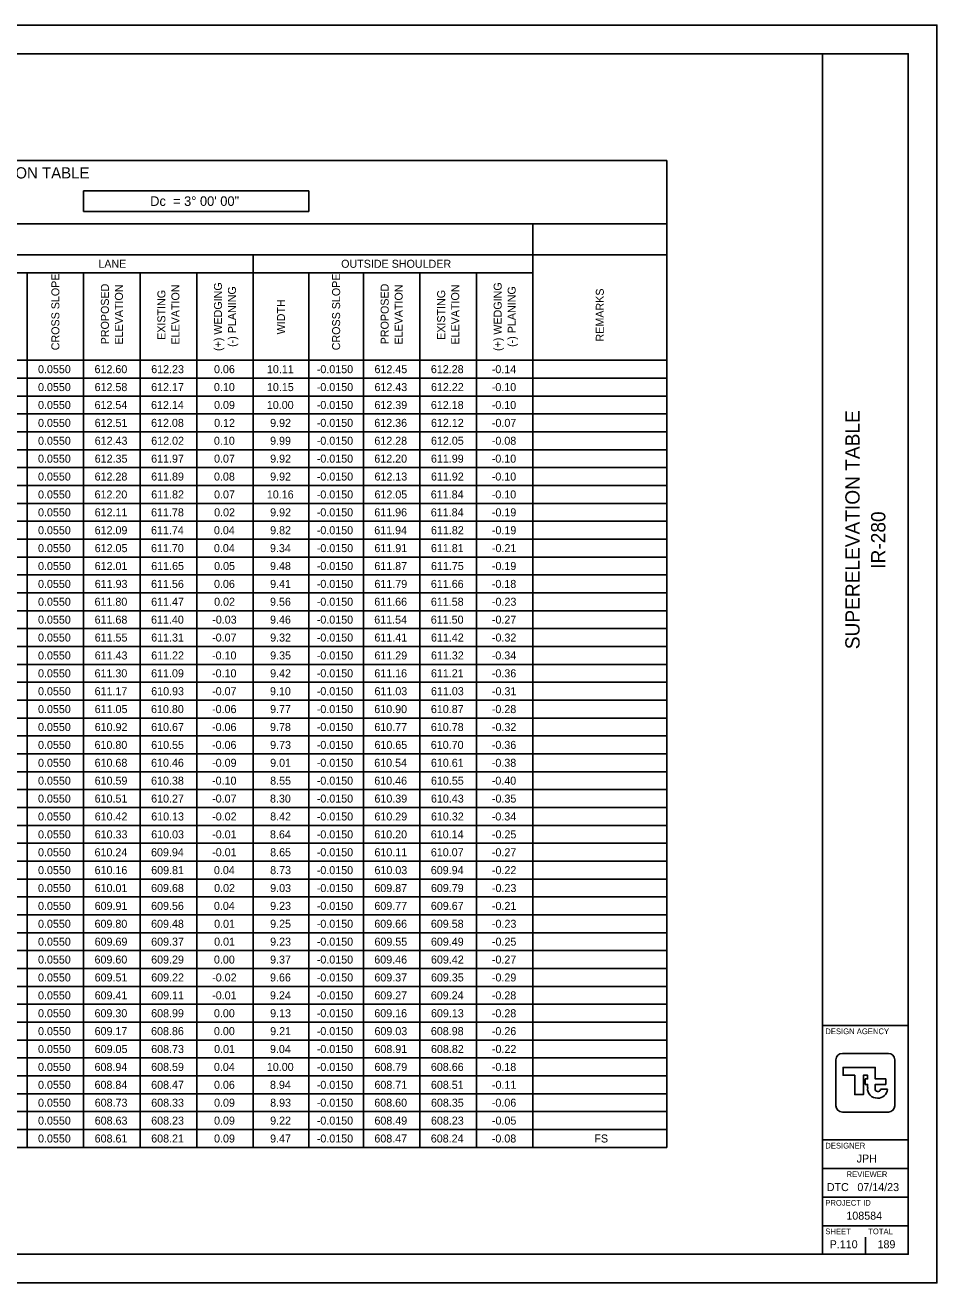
# Model space of a CAD drawing. Extents: x 0 to 34, y 0 to 22.
# Drawn here: x 18.06 to 34, y 0 to 22 of the extents above; entities that cross this region are included whole.
import ezdxf

# ---------------------------------------------------------------- set-up
doc = ezdxf.new("R2010")
doc.units = 0
for name, color, linetype in [('Default', 7, 'Continuous'), ('SH_Border', 7, 'Continuous'), ('SH_Cut_Line', 7, 'Continuous'), ('SH_Data', 7, 'Continuous')]:
    doc.layers.add(name, color=color, linetype=linetype)

msp = doc.modelspace()

# ---------------------------------------------------------------- linework, layer by layer
at = {"layer": 'Default'}
for p, q in [((4.225, 19.63), (29.277, 19.63)), ((29.277, 19.63), (29.277, 2.369)), ((19.081, 19.103), (23.018, 19.103)), ((19.081, 19.103), (19.081, 18.741)), ((23.018, 19.103), (23.018, 18.741)), ((19.081, 18.741), (23.018, 18.741)), ((4.225, 18.526), (29.277, 18.526)), ((26.938, 18.526), (26.938, 2.369)), ((4.225, 17.983), (29.277, 17.983)), ((22.046, 17.983), (22.046, 2.369)), ((6.3, 17.67), (26.938, 17.67)), ((18.093, 17.67), (18.093, 2.369)), ((19.081, 17.67), (19.081, 2.369)), ((20.07, 17.67), (20.07, 2.369)), ((21.058, 17.67), (21.058, 2.369)), ((23.018, 17.67), (23.018, 2.369)), ((23.973, 17.67), (23.973, 2.369)), ((24.961, 17.67), (24.961, 2.369)), ((25.95, 17.67), (25.95, 2.369)), ((4.225, 16.138), (29.277, 16.138)), ((4.225, 15.825), (29.277, 15.825)), ((4.225, 15.512), (29.277, 15.512)), ((4.225, 15.199), (29.277, 15.199)), ((4.225, 14.886), (29.277, 14.886)), ((4.225, 14.574), (29.277, 14.574)), ((4.225, 14.261), (29.277, 14.261)), ((4.225, 13.948), (29.277, 13.948)), ((4.225, 13.635), (29.277, 13.635)), ((4.225, 13.322), (29.277, 13.322)), ((4.225, 13.009), (29.277, 13.009)), ((4.225, 12.696), (29.277, 12.696)), ((4.225, 12.383), (29.277, 12.383)), ((4.225, 12.07), (29.277, 12.07)), ((4.225, 11.757), (29.277, 11.757)), ((4.225, 11.444), (29.277, 11.444)), ((4.225, 11.131), (29.277, 11.131)), ((4.225, 10.818), (29.277, 10.818)), ((4.225, 10.505), (29.277, 10.505)), ((4.225, 10.192), (29.277, 10.192)), ((4.225, 9.879), (29.277, 9.879)), ((4.225, 9.566), (29.277, 9.566)), ((4.225, 9.254), (29.277, 9.254)), ((4.225, 8.941), (29.277, 8.941)), ((4.225, 8.628), (29.277, 8.628)), ((4.225, 8.315), (29.277, 8.315)), ((4.225, 8.002), (29.277, 8.002)), ((4.225, 7.689), (29.277, 7.689)), ((4.225, 7.376), (29.277, 7.376)), ((4.225, 7.063), (29.277, 7.063)), ((4.225, 6.75), (29.277, 6.75)), ((4.225, 6.437), (29.277, 6.437)), ((4.225, 6.124), (29.277, 6.124)), ((4.225, 5.811), (29.277, 5.811)), ((4.225, 5.498), (29.277, 5.498)), ((4.225, 5.185), (29.277, 5.185)), ((4.225, 4.872), (29.277, 4.872)), ((4.225, 4.559), (29.277, 4.559)), ((4.225, 4.246), (29.277, 4.246)), ((4.225, 3.934), (29.277, 3.934)), ((4.225, 3.621), (29.277, 3.621)), ((4.225, 3.308), (29.277, 3.308)), ((4.225, 2.995), (29.277, 2.995)), ((4.225, 2.682), (29.277, 2.682)), ((4.225, 2.369), (29.277, 2.369))]:
    msp.add_line(p, q, dxfattribs=at)
at = {"layer": 'SH_Border'}
for p, q in [((32, 0.5), (32, 21.5)), ((32, 4.5), (33.5, 4.5)), ((32, 2.5), (33.5, 2.5)), ((32, 2), (33.5, 2)), ((32, 1.5), (33.5, 1.5)), ((32, 1), (33.5, 1))]:
    msp.add_line(p, q, dxfattribs=at)
msp.add_lwpolyline([(1.5, 21.5), (33.5, 21.5), (33.5, 0.5), (1.5, 0.5)], close=True, dxfattribs=at)
at = {"layer": 'SH_Cut_Line'}
msp.add_lwpolyline([(0, 0), (34, 0), (34, 22), (0, 22)], close=True, dxfattribs=at)
at = {"layer": 'SH_Data'}
for p, q in [((32.75, 3.5), (32.75, 3.5)), ((32.791, 3.415), (32.791, 3.415)), ((33.136, 3.385), (33.015, 3.385)), ((32.375, 0.675), (32.375, 0.675)), ((32.75, 0.5), (32.75, 0.8))]:
    msp.add_line(p, q, dxfattribs=at)
for points in [[(32.348, 4.014), (33.152, 4.014)], [(32.236, 3.099), (32.236, 3.901)], [(32.922, 3.399), (32.922, 3.47), (33.107, 3.47), (33.107, 3.568), (32.922, 3.568), (32.922, 3.768), (32.361, 3.768), (32.361, 3.632), (32.566, 3.632), (32.566, 3.294), (32.715, 3.294), (32.715, 3.63), (32.79, 3.63), (32.79, 3.568), (32.748, 3.568), (32.748, 3.47), (32.79, 3.47), (32.79, 3.415), (32.791, 3.415)], [(33.264, 3.901), (33.264, 3.099)], [(33.152, 2.986), (32.348, 2.986)]]:
    msp.add_lwpolyline(points, dxfattribs=at)
for centre, radius, start, end in [((32.348, 3.901), 0.113, 90, 180), ((33.152, 3.901), 0.113, 360, 90), ((32.949, 3.392), 0.16, 171.8856, 274.8323), ((32.968, 3.392), 0.0473, 171.8856, 350.9243), ((32.976, 3.392), 0.16, 265.1677, 357.3201), ((32.348, 3.099), 0.113, 180, 270), ((33.152, 3.099), 0.113, 270, 360)]:
    msp.add_arc(centre, radius, start, end, dxfattribs=at)

# ---------------------------------------------------------------- texts
at = {"layer": 'Default'}
for s, height, p in [('WOO/LUC-280-06.20/00.00 - SUPERELEVATION TABLE', 0.196, (12.425, 19.318)), ('Dc  = 3° 00\' 00"', 0.168, (20.245, 18.838)), ('LANE', 0.14, (19.338, 17.756)), ('OUTSIDE SHOULDER', 0.14, (23.584, 17.756)), ('0.0550', 0.14, (18.284, 15.912)), ('612.60', 0.14, (19.272, 15.912)), ('612.23', 0.14, (20.263, 15.912)), ('0.06', 0.14, (21.361, 15.912)), ('10.11', 0.14, (22.287, 15.912)), ('-0.0150', 0.14, (23.158, 15.912)), ('612.45', 0.14, (24.167, 15.912)), ('612.28', 0.14, (25.153, 15.912)), ('-0.14', 0.14, (26.218, 15.912)), ('0.0550', 0.14, (18.284, 15.599)), ('612.58', 0.14, (19.273, 15.599)), ('612.17', 0.14, (20.262, 15.599)), ('0.10', 0.14, (21.36, 15.599)), ('10.15', 0.14, (22.287, 15.599)), ('-0.0150', 0.14, (23.158, 15.599)), ('612.43', 0.14, (24.167, 15.599)), ('612.22', 0.14, (25.155, 15.599)), ('-0.10', 0.14, (26.218, 15.599)), ('0.0550', 0.14, (18.284, 15.286)), ('612.54', 0.14, (19.272, 15.286)), ('612.14', 0.14, (20.26, 15.286)), ('0.09', 0.14, (21.362, 15.286)), ('10.00', 0.14, (22.285, 15.286)), ('-0.0150', 0.14, (23.158, 15.286)), ('612.39', 0.14, (24.166, 15.286)), ('612.18', 0.14, (25.153, 15.286)), ('-0.10', 0.14, (26.218, 15.286)), ('0.0550', 0.14, (18.284, 14.973)), ('612.51', 0.14, (19.274, 14.973)), ('612.08', 0.14, (20.261, 14.973)), ('0.12', 0.14, (21.363, 14.973)), ('9.92', 0.14, (22.343, 14.973)), ('-0.0150', 0.14, (23.158, 14.973)), ('612.36', 0.14, (24.164, 14.973)), ('612.12', 0.14, (25.155, 14.973)), ('-0.07', 0.14, (26.22, 14.973)), ('0.0550', 0.14, (18.284, 14.66)), ('612.43', 0.14, (19.275, 14.66)), ('612.02', 0.14, (20.263, 14.66)), ('0.10', 0.14, (21.36, 14.66)), ('9.99', 0.14, (22.342, 14.66)), ('-0.0150', 0.14, (23.158, 14.66)), ('612.28', 0.14, (24.165, 14.66)), ('612.05', 0.14, (25.155, 14.66)), ('-0.08', 0.14, (26.219, 14.66)), ('0.0550', 0.14, (18.284, 14.347)), ('612.35', 0.14, (19.275, 14.347)), ('611.97', 0.14, (20.262, 14.347)), ('0.07', 0.14, (21.362, 14.347)), ('9.92', 0.14, (22.343, 14.347)), ('-0.0150', 0.14, (23.158, 14.347)), ('612.20', 0.14, (24.164, 14.347)), ('611.99', 0.14, (25.154, 14.347)), ('-0.10', 0.14, (26.218, 14.347)), ('0.0550', 0.14, (18.284, 14.034)), ('612.28', 0.14, (19.273, 14.034)), ('611.89', 0.14, (20.262, 14.034)), ('0.08', 0.14, (21.361, 14.034)), ('9.92', 0.14, (22.343, 14.034)), ('-0.0150', 0.14, (23.158, 14.034)), ('612.13', 0.14, (24.167, 14.034)), ('611.92', 0.14, (25.155, 14.034)), ('-0.10', 0.14, (26.218, 14.034)), ('0.0550', 0.14, (18.284, 13.721)), ('612.20', 0.14, (19.272, 13.721)), ('611.82', 0.14, (20.263, 13.721)), ('0.07', 0.14, (21.362, 13.721)), ('10.16', 0.14, (22.285, 13.721)), ('-0.0150', 0.14, (23.158, 13.721)), ('612.05', 0.14, (24.167, 13.721)), ('611.84', 0.14, (25.152, 13.721)), ('-0.10', 0.14, (26.218, 13.721)), ('0.0550', 0.14, (18.284, 13.408)), ('612.11', 0.14, (19.274, 13.408)), ('611.78', 0.14, (20.261, 13.408)), ('0.02', 0.14, (21.363, 13.408)), ('9.92', 0.14, (22.343, 13.408)), ('-0.0150', 0.14, (23.158, 13.408)), ('611.96', 0.14, (24.164, 13.408)), ('611.84', 0.14, (25.152, 13.408)), ('-0.19', 0.14, (26.22, 13.408)), ('0.0550', 0.14, (18.284, 13.095)), ('612.09', 0.14, (19.274, 13.095)), ('611.74', 0.14, (20.26, 13.095)), ('0.04', 0.14, (21.36, 13.095)), ('9.82', 0.14, (22.343, 13.095)), ('-0.0150', 0.14, (23.158, 13.095)), ('611.94', 0.14, (24.163, 13.095)), ('611.82', 0.14, (25.155, 13.095)), ('-0.19', 0.14, (26.22, 13.095)), ('0.0550', 0.14, (18.284, 12.782)), ('612.05', 0.14, (19.275, 12.782)), ('611.70', 0.14, (20.26, 12.782)), ('0.04', 0.14, (21.36, 12.782)), ('9.34', 0.14, (22.34, 12.782)), ('-0.0150', 0.14, (23.158, 12.782)), ('611.91', 0.14, (24.166, 12.782)), ('611.81', 0.14, (25.154, 12.782)), ('-0.21', 0.14, (26.221, 12.782)), ('0.0550', 0.14, (18.284, 12.469)), ('612.01', 0.14, (19.274, 12.469)), ('611.65', 0.14, (20.263, 12.469)), ('0.05', 0.14, (21.363, 12.469)), ('9.48', 0.14, (22.341, 12.469)), ('-0.0150', 0.14, (23.158, 12.469)), ('611.87', 0.14, (24.165, 12.469)), ('611.75', 0.14, (25.155, 12.469)), ('-0.19', 0.14, (26.22, 12.469)), ('0.0550', 0.14, (18.284, 12.156)), ('611.93', 0.14, (19.275, 12.156)), ('611.56', 0.14, (20.261, 12.156)), ('0.06', 0.14, (21.361, 12.156)), ('9.41', 0.14, (22.343, 12.156)), ('-0.0150', 0.14, (23.158, 12.156)), ('611.79', 0.14, (24.166, 12.156)), ('611.66', 0.14, (25.153, 12.156)), ('-0.18', 0.14, (26.219, 12.156)), ('0.0550', 0.14, (18.284, 11.844)), ('611.80', 0.14, (19.272, 11.844)), ('611.47', 0.14, (20.262, 11.844)), ('0.02', 0.14, (21.363, 11.844)), ('9.56', 0.14, (22.341, 11.844)), ('-0.0150', 0.14, (23.158, 11.844)), ('611.66', 0.14, (24.164, 11.844)), ('611.58', 0.14, (25.153, 11.844)), ('-0.23', 0.14, (26.221, 11.844)), ('0.0550', 0.14, (18.284, 11.531)), ('611.68', 0.14, (19.273, 11.531)), ('611.40', 0.14, (20.26, 11.531)), ('-0.03', 0.14, (21.33, 11.531)), ('9.46', 0.14, (22.341, 11.531)), ('-0.0150', 0.14, (23.158, 11.531)), ('611.54', 0.14, (24.163, 11.531)), ('611.50', 0.14, (25.152, 11.531)), ('-0.27', 0.14, (26.22, 11.531)), ('0.0550', 0.14, (18.284, 11.218)), ('611.55', 0.14, (19.275, 11.218)), ('611.31', 0.14, (20.263, 11.218)), ('-0.07', 0.14, (21.328, 11.218)), ('9.32', 0.14, (22.343, 11.218)), ('-0.0150', 0.14, (23.158, 11.218)), ('611.41', 0.14, (24.166, 11.218)), ('611.42', 0.14, (25.155, 11.218)), ('-0.32', 0.14, (26.221, 11.218)), ('0.0550', 0.14, (18.284, 10.905)), ('611.43', 0.14, (19.275, 10.905)), ('611.22', 0.14, (20.263, 10.905)), ('-0.10', 0.14, (21.327, 10.905)), ('9.35', 0.14, (22.343, 10.905)), ('-0.0150', 0.14, (23.158, 10.905)), ('611.29', 0.14, (24.166, 10.905)), ('611.32', 0.14, (25.155, 10.905)), ('-0.34', 0.14, (26.218, 10.905)), ('0.0550', 0.14, (18.284, 10.592)), ('611.30', 0.14, (19.272, 10.592)), ('611.09', 0.14, (20.262, 10.592)), ('-0.10', 0.14, (21.327, 10.592)), ('9.42', 0.14, (22.343, 10.592)), ('-0.0150', 0.14, (23.158, 10.592)), ('611.16', 0.14, (24.164, 10.592)), ('611.21', 0.14, (25.154, 10.592)), ('-0.36', 0.14, (26.219, 10.592)), ('0.0550', 0.14, (18.284, 10.279)), ('611.17', 0.14, (19.273, 10.279)), ('610.93', 0.14, (20.263, 10.279)), ('-0.07', 0.14, (21.328, 10.279)), ('9.10', 0.14, (22.34, 10.279)), ('-0.0150', 0.14, (23.158, 10.279)), ('611.03', 0.14, (24.167, 10.279)), ('611.03', 0.14, (25.155, 10.279)), ('-0.31', 0.14, (26.221, 10.279)), ('0.0550', 0.14, (18.284, 9.966)), ('611.05', 0.14, (19.275, 9.966)), ('610.80', 0.14, (20.26, 9.966)), ('-0.06', 0.14, (21.327, 9.966)), ('9.77', 0.14, (22.342, 9.966)), ('-0.0150', 0.14, (23.158, 9.966)), ('610.90', 0.14, (24.164, 9.966)), ('610.87', 0.14, (25.153, 9.966)), ('-0.28', 0.14, (26.219, 9.966)), ('0.0550', 0.14, (18.284, 9.653)), ('610.92', 0.14, (19.275, 9.653)), ('610.67', 0.14, (20.262, 9.653)), ('-0.06', 0.14, (21.327, 9.653)), ('9.78', 0.14, (22.341, 9.653)), ('-0.0150', 0.14, (23.158, 9.653)), ('610.77', 0.14, (24.165, 9.653)), ('610.78', 0.14, (25.153, 9.653)), ('-0.32', 0.14, (26.221, 9.653)), ('0.0550', 0.14, (18.284, 9.34)), ('610.80', 0.14, (19.272, 9.34)), ('610.55', 0.14, (20.263, 9.34)), ('-0.06', 0.14, (21.327, 9.34)), ('9.73', 0.14, (22.343, 9.34)), ('-0.0150', 0.14, (23.158, 9.34)), ('610.65', 0.14, (24.167, 9.34)), ('610.70', 0.14, (25.152, 9.34)), ('-0.36', 0.14, (26.219, 9.34)), ('0.0550', 0.14, (18.284, 9.027)), ('610.68', 0.14, (19.273, 9.027)), ('610.46', 0.14, (20.261, 9.027)), ('-0.09', 0.14, (21.328, 9.027)), ('9.01', 0.14, (22.343, 9.027)), ('-0.0150', 0.14, (23.158, 9.027)), ('610.54', 0.14, (24.163, 9.027)), ('610.61', 0.14, (25.154, 9.027)), ('-0.38', 0.14, (26.219, 9.027)), ('0.0550', 0.14, (18.284, 8.714)), ('610.59', 0.14, (19.274, 8.714)), ('610.38', 0.14, (20.261, 8.714)), ('-0.10', 0.14, (21.327, 8.714)), ('8.55', 0.14, (22.343, 8.714)), ('-0.0150', 0.14, (23.158, 8.714)), ('610.46', 0.14, (24.164, 8.714)), ('610.55', 0.14, (25.155, 8.714)), ('-0.40', 0.14, (26.218, 8.714)), ('0.0550', 0.14, (18.284, 8.401)), ('610.51', 0.14, (19.274, 8.401)), ('610.27', 0.14, (20.262, 8.401)), ('-0.07', 0.14, (21.328, 8.401)), ('8.30', 0.14, (22.34, 8.401)), ('-0.0150', 0.14, (23.158, 8.401)), ('610.39', 0.14, (24.166, 8.401)), ('610.43', 0.14, (25.155, 8.401)), ('-0.35', 0.14, (26.221, 8.401)), ('0.0550', 0.14, (18.284, 8.088)), ('610.42', 0.14, (19.275, 8.088)), ('610.13', 0.14, (20.263, 8.088)), ('-0.02', 0.14, (21.329, 8.088)), ('8.42', 0.14, (22.343, 8.088)), ('-0.0150', 0.14, (23.158, 8.088)), ('610.29', 0.14, (24.166, 8.088)), ('610.32', 0.14, (25.155, 8.088)), ('-0.34', 0.14, (26.218, 8.088)), ('0.0550', 0.14, (18.284, 7.775)), ('610.33', 0.14, (19.275, 7.775)), ('610.03', 0.14, (20.263, 7.775)), ('-0.01', 0.14, (21.329, 7.775)), ('8.64', 0.14, (22.34, 7.775)), ('-0.0150', 0.14, (23.158, 7.775)), ('610.20', 0.14, (24.164, 7.775)), ('610.14', 0.14, (25.152, 7.775)), ('-0.25', 0.14, (26.221, 7.775)), ('0.0550', 0.14, (18.284, 7.462)), ('610.24', 0.14, (19.272, 7.462)), ('609.94', 0.14, (20.26, 7.462)), ('-0.01', 0.14, (21.329, 7.462)), ('8.65', 0.14, (22.343, 7.462)), ('-0.0150', 0.14, (23.158, 7.462)), ('610.11', 0.14, (24.166, 7.462)), ('610.07', 0.14, (25.153, 7.462)), ('-0.27', 0.14, (26.22, 7.462)), ('0.0550', 0.14, (18.284, 7.149)), ('610.16', 0.14, (19.273, 7.149)), ('609.81', 0.14, (20.263, 7.149)), ('0.04', 0.14, (21.36, 7.149)), ('8.73', 0.14, (22.343, 7.149)), ('-0.0150', 0.14, (23.158, 7.149)), ('610.03', 0.14, (24.167, 7.149)), ('609.94', 0.14, (25.152, 7.149)), ('-0.22', 0.14, (26.221, 7.149)), ('0.0550', 0.14, (18.284, 6.836)), ('610.01', 0.14, (19.274, 6.836)), ('609.68', 0.14, (20.261, 6.836)), ('0.02', 0.14, (21.363, 6.836)), ('9.03', 0.14, (22.343, 6.836)), ('-0.0150', 0.14, (23.158, 6.836)), ('609.87', 0.14, (24.165, 6.836)), ('609.79', 0.14, (25.154, 6.836)), ('-0.23', 0.14, (26.221, 6.836)), ('0.0550', 0.14, (18.284, 6.524)), ('609.91', 0.14, (19.274, 6.524)), ('609.56', 0.14, (20.261, 6.524)), ('0.04', 0.14, (21.36, 6.524)), ('9.23', 0.14, (22.343, 6.524)), ('-0.0150', 0.14, (23.158, 6.524)), ('609.77', 0.14, (24.165, 6.524)), ('609.67', 0.14, (25.153, 6.524)), ('-0.21', 0.14, (26.221, 6.524)), ('0.0550', 0.14, (18.284, 6.211)), ('609.80', 0.14, (19.272, 6.211)), ('609.48', 0.14, (20.261, 6.211)), ('0.01', 0.14, (21.363, 6.211)), ('9.25', 0.14, (22.343, 6.211)), ('-0.0150', 0.14, (23.158, 6.211)), ('609.66', 0.14, (24.164, 6.211)), ('609.58', 0.14, (25.153, 6.211)), ('-0.23', 0.14, (26.221, 6.211)), ('0.0550', 0.14, (18.284, 5.898)), ('609.69', 0.14, (19.274, 5.898)), ('609.37', 0.14, (20.262, 5.898)), ('0.01', 0.14, (21.363, 5.898)), ('9.23', 0.14, (22.343, 5.898)), ('-0.0150', 0.14, (23.158, 5.898)), ('609.55', 0.14, (24.167, 5.898)), ('609.49', 0.14, (25.154, 5.898)), ('-0.25', 0.14, (26.221, 5.898)), ('0.0550', 0.14, (18.284, 5.585)), ('609.60', 0.14, (19.272, 5.585)), ('609.29', 0.14, (20.262, 5.585)), ('0.00', 0.14, (21.36, 5.585)), ('9.37', 0.14, (22.342, 5.585)), ('-0.0150', 0.14, (23.158, 5.585)), ('609.46', 0.14, (24.164, 5.585)), ('609.42', 0.14, (25.155, 5.585)), ('-0.27', 0.14, (26.22, 5.585)), ('0.0550', 0.14, (18.284, 5.272)), ('609.51', 0.14, (19.274, 5.272)), ('609.22', 0.14, (20.263, 5.272)), ('-0.02', 0.14, (21.329, 5.272)), ('9.66', 0.14, (22.341, 5.272)), ('-0.0150', 0.14, (23.158, 5.272)), ('609.37', 0.14, (24.165, 5.272)), ('609.35', 0.14, (25.155, 5.272)), ('-0.29', 0.14, (26.22, 5.272)), ('0.0550', 0.14, (18.284, 4.959)), ('609.41', 0.14, (19.274, 4.959)), ('609.11', 0.14, (20.263, 4.959)), ('-0.01', 0.14, (21.329, 4.959)), ('9.24', 0.14, (22.34, 4.959)), ('-0.0150', 0.14, (23.158, 4.959)), ('609.27', 0.14, (24.165, 4.959)), ('609.24', 0.14, (25.152, 4.959)), ('-0.28', 0.14, (26.219, 4.959)), ('0.0550', 0.14, (18.284, 4.646)), ('609.30', 0.14, (19.272, 4.646)), ('608.99', 0.14, (20.262, 4.646)), ('0.00', 0.14, (21.36, 4.646)), ('9.13', 0.14, (22.343, 4.646)), ('-0.0150', 0.14, (23.158, 4.646)), ('609.16', 0.14, (24.164, 4.646)), ('609.13', 0.14, (25.155, 4.646)), ('-0.28', 0.14, (26.219, 4.646)), ('0.0550', 0.14, (18.284, 4.333)), ('609.17', 0.14, (19.273, 4.333)), ('608.86', 0.14, (20.261, 4.333)), ('0.00', 0.14, (21.36, 4.333)), ('9.21', 0.14, (22.343, 4.333)), ('-0.0150', 0.14, (23.158, 4.333)), ('609.03', 0.14, (24.167, 4.333)), ('608.98', 0.14, (25.153, 4.333)), ('-0.26', 0.14, (26.219, 4.333)), ('0.0550', 0.14, (18.284, 4.02)), ('609.05', 0.14, (19.275, 4.02)), ('608.73', 0.14, (20.263, 4.02)), ('0.01', 0.14, (21.363, 4.02)), ('9.04', 0.14, (22.34, 4.02)), ('-0.0150', 0.14, (23.158, 4.02)), ('608.91', 0.14, (24.166, 4.02)), ('608.82', 0.14, (25.155, 4.02)), ('-0.22', 0.14, (26.221, 4.02)), ('0.0550', 0.14, (18.284, 3.707)), ('608.94', 0.14, (19.272, 3.707)), ('608.59', 0.14, (20.262, 3.707)), ('0.04', 0.14, (21.36, 3.707)), ('10.00', 0.14, (22.285, 3.707)), ('-0.0150', 0.14, (23.158, 3.707)), ('608.79', 0.14, (24.166, 3.707)), ('608.66', 0.14, (25.153, 3.707)), ('-0.18', 0.14, (26.219, 3.707)), ('0.0550', 0.14, (18.284, 3.394)), ('608.84', 0.14, (19.272, 3.394)), ('608.47', 0.14, (20.262, 3.394)), ('0.06', 0.14, (21.361, 3.394)), ('8.94', 0.14, (22.34, 3.394)), ('-0.0150', 0.14, (23.158, 3.394)), ('608.71', 0.14, (24.166, 3.394)), ('608.51', 0.14, (25.154, 3.394)), ('-0.11', 0.14, (26.221, 3.394)), ('0.0550', 0.14, (18.284, 3.081)), ('608.73', 0.14, (19.275, 3.081)), ('608.33', 0.14, (20.263, 3.081)), ('0.09', 0.14, (21.362, 3.081)), ('8.93', 0.14, (22.343, 3.081)), ('-0.0150', 0.14, (23.158, 3.081)), ('608.60', 0.14, (24.164, 3.081)), ('608.35', 0.14, (25.155, 3.081)), ('-0.06', 0.14, (26.219, 3.081)), ('0.0550', 0.14, (18.284, 2.768)), ('608.63', 0.14, (19.275, 2.768)), ('608.23', 0.14, (20.263, 2.768)), ('0.09', 0.14, (21.362, 2.768)), ('9.22', 0.14, (22.343, 2.768)), ('-0.0150', 0.14, (23.158, 2.768)), ('608.49', 0.14, (24.166, 2.768)), ('608.23', 0.14, (25.155, 2.768)), ('-0.05', 0.14, (26.221, 2.768)), ('0.0550', 0.14, (18.284, 2.455)), ('608.61', 0.14, (19.274, 2.455)), ('608.21', 0.14, (20.263, 2.455)), ('0.09', 0.14, (21.362, 2.455)), ('9.47', 0.14, (22.342, 2.455)), ('-0.0150', 0.14, (23.158, 2.455)), ('608.47', 0.14, (24.165, 2.455)), ('608.24', 0.14, (25.152, 2.455)), ('-0.08', 0.14, (26.219, 2.455)), ('FS', 0.14, (28.012, 2.455))]:
    msp.add_text(s, height=height, dxfattribs=at).set_placement(p)
for s, p in [('CROSS SLOPE', (18.657, 16.313)), ('CROSS SLOPE', (23.566, 16.313)), ('PROPOSED ', (19.523, 16.417)), ('ELEVATION', (19.768, 16.413)), ('ELEVATION', (20.756, 16.413)), ('(+) WEDGING', (21.5, 16.3)), ('(-) PLANING', (21.745, 16.372)), ('PROPOSED ', (24.415, 16.417)), ('ELEVATION', (24.66, 16.413)), ('ELEVATION', (25.648, 16.413)), ('(+) WEDGING', (26.391, 16.3)), ('(-) PLANING', (26.636, 16.372)), ('REMARKS', (28.177, 16.467)), ('EXISTING ', (20.511, 16.495)), ('WIDTH', (22.602, 16.591)), ('EXISTING ', (25.403, 16.495))]:
    msp.add_text(s, height=0.14, rotation=90, dxfattribs=at).set_placement(p)
at = {"layer": 'SH_Data'}
for s, p in [('SUPERELEVATION TABLE', (32.65, 11.084)), ('IR-280', (33.1, 12.491))]:
    msp.add_text(s, height=0.25, rotation=90, dxfattribs=at).set_placement(p)
for s, height, p in [('DESIGN AGENCY', 0.1, (32.05, 4.35)), ('DESIGNER', 0.1, (32.05, 2.35)), ('JPH', 0.14, (32.598, 2.105)), ('REVIEWER', 0.1, (32.422, 1.85)), ('DTC', 0.14, (32.076, 1.605)), ('07/14/23', 0.14, (32.611, 1.605)), ('PROJECT ID', 0.1, (32.05, 1.35)), ('108584', 0.14, (32.418, 1.105)), ('SHEET', 0.1, (32.05, 0.85)), ('TOTAL', 0.1, (32.8, 0.85)), ('P.110', 0.14, (32.126, 0.605)), ('189', 0.14, (32.963, 0.605))]:
    msp.add_text(s, height=height, dxfattribs=at).set_placement(p)

doc.saveas('drawing.dxf')
